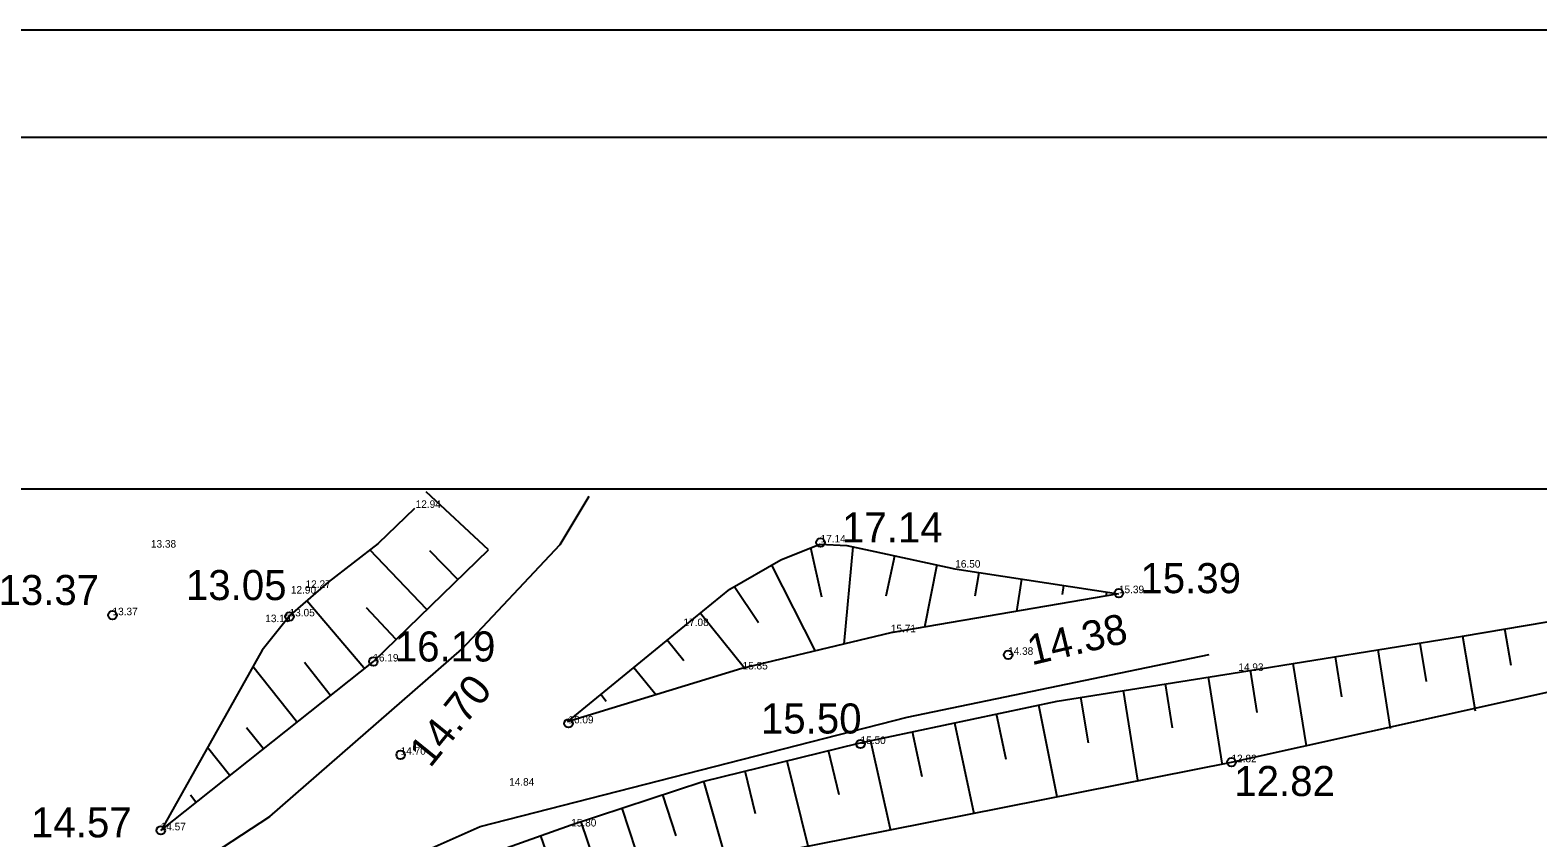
# Model space of a CAD drawing. Extents: x 433497 to 434382, y 6534486 to 6534993.
# Drawn here: x 433944.7 to 434014.9, y 6534945.5 to 6534983.1 of the extents above; entities that cross this region are included whole.
import ezdxf

# ---------------------------------------------------------------- set-up
doc = ezdxf.new("R2010")
doc.units = 0
for name, color, linetype in [('KORGUS-EH2000', 7, 'Continuous'), ('MOOTKORG-EH2000', 7, 'Continuous'), ('RELJEEF', 7, 'Continuous'), ('TEE', 7, 'Continuous'), ('VORMISTUS', 7, 'Continuous')]:
    doc.layers.add(name, color=color, linetype=linetype)

msp = doc.modelspace()

# ---------------------------------------------------------------- linework, layer by layer
at = {"layer": 'KORGUS-EH2000'}
for centre in [(433981.48, 6534959.22), (433995.37, 6534956.86), (433948.517, 6534955.833), (433956.76, 6534955.78), (433960.66, 6534953.68), (433990.21, 6534953.99), (433969.74, 6534950.8), (433961.93, 6534949.34), (433983.34, 6534949.84), (434000.61, 6534948.99), (433950.76, 6534945.82)]:
    msp.add_circle(centre, 0.2, dxfattribs=at)
at = {"layer": 'RELJEEF'}
for p, q in [((433966.025, 6534958.879), (433963.122, 6534961.574)), ((433963.142, 6534956.107), (433960.497, 6534958.879)), ((433963.278, 6534958.852), (433964.586, 6534957.49)), ((433981.539, 6534956.668), (433981.022, 6534958.972)), ((433982.981, 6534959.016), (433982.556, 6534954.482)), ((433979.198, 6534958.16), (433981.227, 6534954.166)), ((433984.533, 6534956.729), (433984.937, 6534958.6)), ((433986.891, 6534958.172), (433986.311, 6534955.274)), ((433988.677, 6534956.732), (433988.858, 6534957.816)), ((433990.835, 6534957.515), (433990.606, 6534956.012)), ((433978.594, 6534955.486), (433977.464, 6534957.164)), ((433992.748, 6534956.791), (433992.812, 6534957.214)), ((433994.789, 6534956.913), (433994.761, 6534956.726)), ((433995.351, 6534956.827), (433995.351, 6534956.827)), ((433960.216, 6534953.381), (433957.556, 6534956.5)), ((433960.321, 6534956.201), (433961.693, 6534954.728)), ((433975.891, 6534955.934), (433977.931, 6534953.381)), ((434013.632, 6534953.496), (434013.341, 6534955.194)), ((433975.119, 6534953.718), (433974.342, 6534954.669)), ((434009.684, 6534952.752), (434009.396, 6534954.533)), ((434011.369, 6534954.856), (434011.952, 6534951.379)), ((434005.745, 6534952.031), (434005.446, 6534953.901)), ((434007.421, 6534954.217), (434008.005, 6534950.565)), ((433957.088, 6534950.889), (433955.055, 6534953.441)), ((433957.449, 6534953.646), (433958.652, 6534952.135)), ((433972.794, 6534953.402), (433973.831, 6534952.134)), ((434001.808, 6534951.311), (434001.496, 6534953.269)), ((434003.471, 6534953.585), (434004.083, 6534949.757)), ((433997.87, 6534950.596), (433997.546, 6534952.642)), ((433999.521, 6534952.955), (434000.156, 6534948.949)), ((433999.521, 6534952.955), (434000.156, 6534948.949)), ((433971.505, 6534951.819), (433971.246, 6534952.136)), ((433991.628, 6534951.656), (433992.472, 6534947.388)), ((433993.958, 6534949.889), (433993.595, 6534952.015)), ((433995.57, 6534952.329), (433996.233, 6534948.152)), ((433990.123, 6534949.121), (433989.672, 6534951.24)), ((433954.761, 6534950.6), (433955.523, 6534949.643)), ((433986.207, 6534948.306), (433985.76, 6534950.407)), ((433987.716, 6534950.823), (433988.614, 6534946.605)), ((433953.959, 6534948.396), (433952.943, 6534949.673)), ((433982.35, 6534947.481), (433981.857, 6534949.53)), ((433983.804, 6534949.99), (433984.74, 6534945.818)), ((433979.915, 6534949.055), (433980.899, 6534945.037)), ((433978.458, 6534946.593), (433977.972, 6534948.579)), ((433952.141, 6534947.469), (433952.395, 6534947.15)), ((433974.76, 6534945.568), (433974.13, 6534947.479)), ((433976.03, 6534948.103), (433977.167, 6534944.132)), ((433972.231, 6534946.852), (433973.457, 6534943.139)), ((433970.941, 6534944.427), (433970.332, 6534946.224)), ((433950.83, 6534945.904), (433950.83, 6534945.904)), ((433968.443, 6534945.567), (433969.651, 6534942.121))]:
    msp.add_line(p, q, dxfattribs=at)
for points in [[(433962.581, 6534960.799), (433960.878, 6534959.176), (433958.559, 6534957.37), (433956.789, 6534955.834), (433955.482, 6534954.204), (433950.83, 6534945.904)], [(433950.76, 6534945.82), (433960.66, 6534953.68), (433966.025, 6534958.879)], [(433969.698, 6534950.869), (433975.16, 6534955.338), (433977.255, 6534957.045), (433979.636, 6534958.411), (433981.449, 6534959.144), (433982.701, 6534959.074), (433984.005, 6534958.805), (433987.738, 6534957.986), (433995.351, 6534956.827)], [(434000.978, 6534953.186), (434011.369, 6534954.856), (434015.312, 6534955.532), (434019.1, 6534956.37), (434023.02, 6534957.634)], [(433995.351, 6534956.827), (433984.759, 6534955.007), (433977.808, 6534953.352), (433969.698, 6534950.869)], [(433954.03, 6534938.79), (433965.22, 6534940.93), (433979.48, 6534944.81), (434000.61, 6534948.99), (434020.069, 6534953.305), (434024.103, 6534954.537)], [(433953.975, 6534938.787), (433960.744, 6534942.298), (433965.248, 6534944.438), (433969.863, 6534946.07), (433975.995, 6534948.095), (433983.269, 6534949.876), (433992.495, 6534951.841), (434000.978, 6534953.186)]]:
    msp.add_lwpolyline(points, dxfattribs=at)
at = {"layer": 'TEE'}
for points in [[(433874.435, 6534945.232), (433884.76, 6534945.232), (433910.905, 6534945.232), (433917.189, 6534944.061), (433920.115, 6534941.134), (433928.637, 6534935.367), (433935.092, 6534933.818), (433941.327, 6534936.101), (433947.573, 6534941.048), (433955.837, 6534946.471), (433964.776, 6534954.254), (433969.351, 6534959.124), (433970.711, 6534961.378)], [(433945.192, 6534928.357), (433948.84, 6534935.416), (433954.459, 6534941.035), (433965.625, 6534946.003), (433985.508, 6534951.082), (433999.574, 6534954.006)]]:
    msp.add_lwpolyline(points, dxfattribs=at)
at = {"layer": 'VORMISTUS'}
for points in [[(433496.616, 6534983.068), (433496.616, 6534486.033), (434381.616, 6534486.033), (434381.616, 6534983.068)], [(434376.616, 6534978.068), (433516.616, 6534978.068), (433516.616, 6534491.033), (434376.616, 6534491.033)]]:
    msp.add_lwpolyline(points, close=True, dxfattribs=at)
msp.add_lwpolyline([(434105.076, 6534919.645), (434021.466, 6534961.703), (433907.235, 6534961.703), (433895.612, 6534963.725), (433866.629, 6534959.596), (433850.026, 6534935.498), (433840.916, 6534926.387), (433788.144, 6534906.278), (433769.653, 6534899.233), (433756.833, 6534894.348), (433691.203, 6534872.087)], dxfattribs=at)
msp.add_lwpolyline([(434105.076, 6534919.645), (434021.466, 6534961.703), (433907.235, 6534961.703), (433895.612, 6534963.725), (433866.629, 6534959.596), (433850.026, 6534935.498), (433840.916, 6534926.387), (433788.144, 6534906.278), (433769.653, 6534899.233), (433756.833, 6534894.348), (433691.203, 6534872.087)], dxfattribs=at)

# ---------------------------------------------------------------- texts
at = {"layer": 'KORGUS-EH2000'}
for s, p in [('17.14', (433982.48, 6534959.22)), ('13.05', (433951.934, 6534956.538)), ('15.39', (433996.37, 6534956.86)), ('13.37', (433943.207, 6534956.309)), ('16.19', (433961.66, 6534953.68)), ('15.50', (433978.703, 6534950.328)), ('12.82', (434000.74, 6534947.417)), ('14.57', (433944.724, 6534945.492))]:
    msp.add_text(s, height=1.4, dxfattribs=at).set_placement(p)
for s, rotation, p in [('14.38', 13.39243, (433991.303, 6534953.497)), ('14.70', 51.02739, (433963.304, 6534948.688))]:
    msp.add_text(s, height=1.4, rotation=rotation, dxfattribs=at).set_placement(p)
at = {"layer": 'MOOTKORG-EH2000'}
for s, p in [('12.94', (433962.63, 6534960.83)), ('17.14', (433981.48, 6534959.22)), ('13.38', (433950.306, 6534958.98)), ('16.50', (433987.75, 6534958.05)), ('12.27', (433957.505, 6534957.108)), ('12.90', (433956.82, 6534956.84)), ('15.39', (433995.37, 6534956.86)), ('13.37', (433948.517, 6534955.833)), ('13.19', (433955.629, 6534955.512)), ('13.05', (433956.76, 6534955.78)), ('17.08', (433975.1, 6534955.33)), ('15.71', (433984.75, 6534955.04)), ('16.19', (433960.66, 6534953.68)), ('14.38', (433990.21, 6534953.99)), ('15.85', (433977.85, 6534953.31)), ('14.93', (434000.93, 6534953.24)), ('16.09', (433969.74, 6534950.8)), ('14.70', (433961.93, 6534949.34)), ('15.50', (433983.34, 6534949.84)), ('12.82', (434000.61, 6534948.99)), ('14.84', (433966.98, 6534947.9)), ('14.57', (433950.76, 6534945.82)), ('15.80', (433969.87, 6534946))]:
    msp.add_text(s, height=0.35, dxfattribs=at).set_placement(p)

doc.saveas('drawing.dxf')
